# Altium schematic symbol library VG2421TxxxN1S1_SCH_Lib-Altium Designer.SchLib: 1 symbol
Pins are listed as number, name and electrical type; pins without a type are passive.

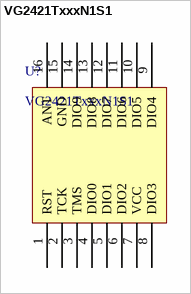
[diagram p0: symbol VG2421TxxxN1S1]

## VG2421TxxxN1S1
designator U?
pins: 1 RST, 2 TCK, 3 TMS, 4 DIO0, 5 DIO1, 6 DIO2, 7 VCC, 8 DIO3, 9 DIO4, 10 DIO5, 11 DIO6, 12 DIO7, 13 DIO8, 14 DIO9, 15 GND, 16 ANT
